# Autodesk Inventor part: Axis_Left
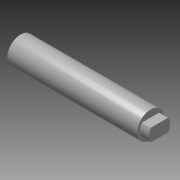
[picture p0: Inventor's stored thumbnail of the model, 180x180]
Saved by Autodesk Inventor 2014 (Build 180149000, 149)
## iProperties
Created: 2006-03
Part Number: Axis_Left
Document SubType Name: Modeling
Designer: debonom
Material: Stainless Steel, 440C
Mass: 103.094 g
Surface Area: 39.6652 cm^2
Volume: 13.3025 cm^3
Density: 7.75 g/cm^3
Appearance: Steel
Author: debonom
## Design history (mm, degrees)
sketch "Sketch1"
  geometry: L1 (-4.823, 3.575)-(4.823, 3.575); L2 (4.823, 3.575)-(4.823, -3.575); L3 (4.823, -3.575)-(-4.822, -3.575); L4 (-4.822, -3.575)-(-4.823, 3.575); L5 (-4.823, 3.575)-(4.823, -3.575); L6 (-8.405, 0)-(8.405, 0) reference; A1 r 6 centre (-0.004, 0) between (-4.823, 3.575) and (-4.822, -3.575); A2 r 6 centre (0.004, 0) between (4.823, -3.575) and (4.823, 3.575); 2 further points
  constraints: 10 end point, 4 point on circle, 2 centre point, 2 parallel, 2 point on line, 1 coincident, 1 equal radius, 1 horizontal, 1 midpoint, 1 perpendicular
  dimensions: "d0" = 9.645 distance of L2.end L3.end; "d1" = 7.15 distance of L3.end L1.start; "d2" = 6 radius of A1
extrude "Extrusion1" new body sketch "Sketch1" distance "d3" = 5; taper "d4" = 0 deg
sketch "Sketch2"
  geometry: C1 r 7.5 at (0, 0); 1 further point
  constraints: 1 centre point, 1 coincident
  dimensions: "d5" = 15 diameter of C1
extrude "Extrusion2" join sketch "Sketch2" distance "d6" = 73; taper "d7" = 0 deg
body "Solid1"
